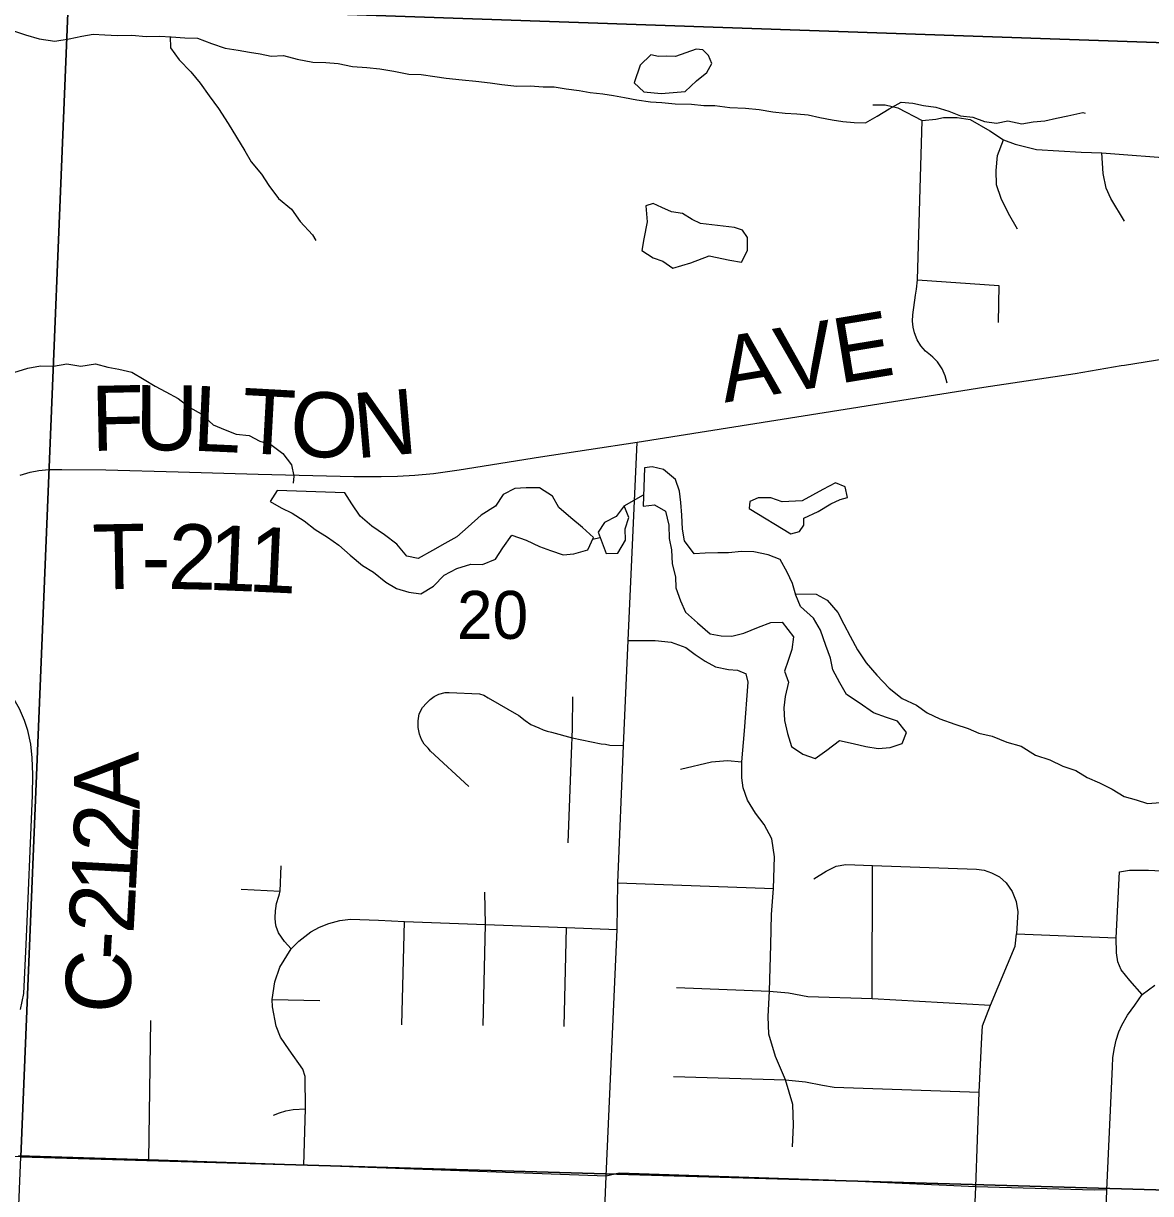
# Model space of a CAD drawing. Extents: x 0 to 34, y 0 to 22.
# Drawn here: x 4.185 to 5.169, y 16.95 to 17.972 of the extents above; entities that cross this region are included whole.
import ezdxf

# ---------------------------------------------------------------- set-up
doc = ezdxf.new("R2010")
doc.units = 0
for name, color, linetype in [('GM_X_Corporation', 7, 'Continuous'), ('GM_X_County_Road', 7, 'Continuous'), ('GM_X_County_Road_Text', 7, 'Continuous'), ('GM_X_Minor_Lake', 7, 'Continuous'), ('GM_X_Minor_River', 7, 'Continuous'), ('GM_X_Section_Text', 7, 'Continuous'), ('GM_X_Township_Road', 7, 'Continuous'), ('GM_X_Township_Road_Text', 7, 'Continuous')]:
    doc.layers.add(name, color=color, linetype=linetype)

msp = doc.modelspace()

# ---------------------------------------------------------------- linework, layer by layer
at = {"layer": 'GM_X_Corporation'}
for points in [[(5.2829, 18.9603), (5.2412, 17.9526), (4.2238, 17.9879), (4.2642, 18.9963)], [(3.1939, 18.0257), (4.2238, 17.9879), (4.1823, 16.9818), (3.1533, 17.0117), (3.155, 17.0299)], [(4.2238, 17.9879), (5.2412, 17.9526), (5.2034, 16.9522), (4.1823, 16.9818)], [(5.2034, 16.9522), (5.1967, 16.4715), (5.1712, 15.9307), (4.1402, 15.964), (4.1823, 16.9818)]]:
    msp.add_lwpolyline(points, close=True, dxfattribs=at)
at = {"layer": 'GM_X_County_Road'}
msp.add_lwpolyline([(4.1822, 17.1107), (4.185, 17.1244), (4.187, 17.1674), (4.1889, 17.2076), (4.1909, 17.2557), (4.1925, 17.2974), (4.1929, 17.3158), (4.1924, 17.3302), (4.1911, 17.3422), (4.1884, 17.3542), (4.1856, 17.3629), (4.1811, 17.3732), (4.1755, 17.3833), (4.169, 17.3936), (4.16, 17.4071), (4.1385, 17.4387), (4.132, 17.4487), (4.1243, 17.4624), (4.1222, 17.4744)], dxfattribs=at)
at = {"layer": 'GM_X_Minor_Lake'}
for points in [[(4.754, 17.9427), (4.7464, 17.943), (4.7392, 17.9426), (4.7324, 17.9441), (4.7233, 17.935), (4.7181, 17.9198), (4.7265, 17.9118), (4.7416, 17.9104), (4.7625, 17.912), (4.7723, 17.9215), (4.7814, 17.9287), (4.7859, 17.9367), (4.7828, 17.9436), (4.7779, 17.9485), (4.7722, 17.9492)], [(4.7722, 17.9492), (4.754, 17.9427)], [(4.7759, 17.797), (4.7687, 17.8004), (4.7603, 17.8057), (4.7505, 17.8072), (4.7421, 17.8109), (4.7345, 17.8143), (4.7281, 17.8124), (4.7293, 17.7983), (4.7263, 17.7835), (4.7248, 17.7733), (4.7347, 17.7669), (4.7431, 17.7639), (4.7518, 17.7578), (4.7674, 17.7624), (4.7836, 17.7686), (4.8015, 17.7648), (4.8117, 17.763), (4.817, 17.7732), (4.8169, 17.7846), (4.8127, 17.7911), (4.8055, 17.7933)], [(4.8055, 17.7933), (4.7759, 17.797)], [(4.7259, 17.5501), (4.7357, 17.5512), (4.7452, 17.5456), (4.7483, 17.5335), (4.7484, 17.5217), (4.7507, 17.5118), (4.7511, 17.4997), (4.7542, 17.4883), (4.7543, 17.4788), (4.7585, 17.4674), (4.7627, 17.4576), (4.7734, 17.4481), (4.7844, 17.4387), (4.7939, 17.4368), (4.8034, 17.4365), (4.8136, 17.4392), (4.8265, 17.4445), (4.8374, 17.4484), (4.8473, 17.4488), (4.8572, 17.4359), (4.8557, 17.4249), (4.8524, 17.4154), (4.8494, 17.4059), (4.8528, 17.3964), (4.8499, 17.3839), (4.8488, 17.374), (4.8492, 17.363), (4.8519, 17.3516), (4.8554, 17.3403), (4.8653, 17.3335), (4.8759, 17.3297), (4.8861, 17.3369), (4.8974, 17.3453), (4.9092, 17.3427), (4.9202, 17.3401), (4.9312, 17.3386), (4.9415, 17.3394), (4.9521, 17.3429), (4.9558, 17.3524), (4.9478, 17.3622), (4.9383, 17.3656), (4.9269, 17.3697), (4.9144, 17.3784), (4.9033, 17.3856), (4.8976, 17.3958), (4.8915, 17.4072), (4.8895, 17.4174), (4.8853, 17.4284), (4.8807, 17.4417), (4.8746, 17.4523), (4.8632, 17.4625), (4.8593, 17.4724), (4.8562, 17.4826), (4.8516, 17.4925), (4.8455, 17.5034), (4.8349, 17.5076), (4.8224, 17.5102), (4.8117, 17.5105), (4.8004, 17.5094), (4.7909, 17.5093), (4.7799, 17.5089), (4.7704, 17.5085), (4.762, 17.5198), (4.7601, 17.5301), (4.7597, 17.5422), (4.7588, 17.5532), (4.7577, 17.5631), (4.7542, 17.5733), (4.7435, 17.582), (4.7337, 17.5843), (4.7269, 17.5835)], [(4.7269, 17.5835), (4.7259, 17.5501)], [(4.4062, 17.5637), (4.4001, 17.5542), (4.4097, 17.5485), (4.4192, 17.544), (4.4298, 17.5372), (4.4393, 17.5296), (4.4503, 17.5229), (4.4602, 17.5161), (4.4701, 17.5074), (4.4808, 17.4983), (4.4903, 17.4923), (4.501, 17.4836), (4.5105, 17.4783), (4.5211, 17.4749), (4.5317, 17.4734), (4.5427, 17.4803), (4.5521, 17.4898), (4.5631, 17.4956), (4.5752, 17.4994), (4.5854, 17.4991), (4.5968, 17.5037), (4.6032, 17.5136), (4.6111, 17.5246), (4.6236, 17.5205), (4.6354, 17.5148), (4.6449, 17.5114), (4.6559, 17.5077), (4.6654, 17.5085), (4.6775, 17.5119), (4.6824, 17.5226), (4.6729, 17.5313), (4.6626, 17.54), (4.6523, 17.549), (4.6466, 17.5589), (4.6352, 17.5661), (4.6238, 17.566), (4.6139, 17.5656), (4.6037, 17.5602), (4.597, 17.55), (4.5845, 17.5423), (4.5731, 17.532), (4.563, 17.5233), (4.5527, 17.5175), (4.5418, 17.5114), (4.5293, 17.5045), (4.5194, 17.5064), (4.5107, 17.517), (4.5, 17.5249), (4.489, 17.5325), (4.4787, 17.5412), (4.4714, 17.5522), (4.4653, 17.5616)], [(4.8549, 17.5259), (4.8625, 17.5278), (4.8662, 17.5335), (4.8662, 17.5396), (4.8787, 17.5453), (4.8897, 17.5522), (4.898, 17.556), (4.9044, 17.5576), (4.9021, 17.567), (4.8938, 17.5704), (4.8828, 17.5647), (4.8646, 17.5548), (4.8472, 17.5539), (4.8373, 17.5573), (4.8263, 17.5573), (4.8191, 17.5542), (4.8184, 17.5481)], [(4.4653, 17.5616), (4.4062, 17.5637)], [(4.6935, 17.5086), (4.7037, 17.509), (4.7105, 17.5204), (4.71, 17.5303), (4.7134, 17.5402), (4.7092, 17.5504), (4.7024, 17.5409), (4.6922, 17.5359), (4.6865, 17.5275)], [(4.8184, 17.5481), (4.8549, 17.5259)], [(4.6865, 17.5275), (4.6935, 17.5086)]]:
    msp.add_lwpolyline(points, dxfattribs=at)
at = {"layer": 'GM_X_Minor_River'}
for points in [[(4.1768, 17.9648), (4.1863, 17.9615), (4.1985, 17.9581), (4.2121, 17.9562), (4.2246, 17.9582), (4.2356, 17.9605), (4.2455, 17.9621), (4.2557, 17.9617), (4.2667, 17.961), (4.2792, 17.9614), (4.2917, 17.9603), (4.3035, 17.9604), (4.3137, 17.96), (4.3255, 17.9589), (4.3365, 17.9586), (4.349, 17.9541), (4.3608, 17.95), (4.3722, 17.9481), (4.382, 17.9466), (4.3915, 17.9451), (4.401, 17.9429), (4.4116, 17.9437), (4.4238, 17.9403), (4.4374, 17.9377), (4.4488, 17.9374), (4.4594, 17.9367), (4.4719, 17.9341), (4.4845, 17.933), (4.4958, 17.9319), (4.508, 17.93), (4.5213, 17.9274), (4.5319, 17.9271), (4.544, 17.9252), (4.5539, 17.9237), (4.5679, 17.9223), (4.5797, 17.9212), (4.5922, 17.9197), (4.6025, 17.9182), (4.6154, 17.9167), (4.6271, 17.9172), (4.6385, 17.9161), (4.648, 17.9161), (4.6586, 17.9146), (4.67, 17.9131), (4.6795, 17.9113), (4.6905, 17.9102), (4.6999, 17.9087), (4.7094, 17.9068), (4.7204, 17.905), (4.7322, 17.9031), (4.7421, 17.9024), (4.7538, 17.9013), (4.7679, 17.901), (4.7789, 17.8999), (4.7883, 17.8999), (4.8016, 17.8981), (4.8153, 17.8977), (4.827, 17.8963), (4.8392, 17.8944), (4.8498, 17.8933), (4.86, 17.8926), (4.8699, 17.8919), (4.8801, 17.8893), (4.8908, 17.8874), (4.9003, 17.8859), (4.9101, 17.8852), (4.92, 17.8848), (4.9302, 17.8906), (4.9408, 17.8971), (4.951, 17.9028), (4.9612, 17.9021), (4.9707, 17.8998), (4.9813, 17.8984), (4.9927, 17.895), (5.003, 17.8908), (5.0136, 17.8897), (5.0239, 17.886), (5.0345, 17.8845), (5.0443, 17.8864), (5.0565, 17.8838), (5.0663, 17.8858), (5.0766, 17.8866), (5.0868, 17.8889), (5.0966, 17.8908), (5.1099, 17.8939), (5.1118, 17.8931)], [(4.3128, 17.9601), (4.313, 17.9502), (4.3206, 17.9399), (4.3309, 17.9294), (4.3389, 17.9195), (4.3469, 17.9085), (4.355, 17.8972), (4.3634, 17.8843), (4.3706, 17.8722), (4.3779, 17.8604), (4.3836, 17.8506), (4.3924, 17.84), (4.3989, 17.8301), (4.4073, 17.8188), (4.4187, 17.8093), (4.4263, 17.7987), (4.437, 17.787), (4.44, 17.7821)], [(4.1763, 17.6668), (4.1884, 17.6707), (4.1994, 17.6726), (4.2108, 17.6723), (4.2225, 17.6742), (4.2347, 17.6724), (4.2475, 17.6743), (4.2582, 17.6713), (4.268, 17.6698), (4.2794, 17.6672), (4.2901, 17.6608), (4.2996, 17.6548), (4.3091, 17.6499), (4.3197, 17.6442), (4.33, 17.6363), (4.3399, 17.6306), (4.3502, 17.6212), (4.3608, 17.6167), (4.3703, 17.6129), (4.3817, 17.6118), (4.3912, 17.6069), (4.4007, 17.6039), (4.4113, 17.596), (4.4186, 17.5861), (4.4209, 17.5763), (4.4202, 17.5701)], [(4.7092, 17.5504), (4.7262, 17.56)], [(4.6817, 17.5212), (4.6883, 17.5228)], [(4.859, 17.4734), (4.8768, 17.4732), (4.8866, 17.4679), (4.8958, 17.4573), (4.9011, 17.4471), (4.9065, 17.4365), (4.913, 17.4247), (4.9206, 17.4134), (4.9298, 17.4024), (4.9408, 17.3911), (4.9519, 17.382), (4.9644, 17.3763), (4.9739, 17.3695), (4.9849, 17.3643), (4.9979, 17.3598), (5.0096, 17.356), (5.0191, 17.3519), (5.0305, 17.3493), (5.0434, 17.344), (5.056, 17.3406), (5.0685, 17.3327), (5.081, 17.3286), (5.0924, 17.3229), (5.1038, 17.3192), (5.1137, 17.3131), (5.1244, 17.3086), (5.1354, 17.3029), (5.146, 17.2965), (5.1563, 17.2935), (5.1662, 17.2905), (5.1775, 17.2913)]]:
    msp.add_lwpolyline(points, dxfattribs=at)
at = {"layer": 'GM_X_Township_Road'}
for p, q in [((4.9258, 17.1201), (4.9262, 17.2364)), ((4.7036, 17.2213), (4.8396, 17.2162)), ((4.3749, 17.2157), (4.4087, 17.2139)), ((4.5151, 17.0973), (4.5174, 17.1874)), ((4.6568, 17.0958), (4.6589, 17.1821)), ((5.052, 17.1765), (5.1388, 17.1731)), ((4.4019, 17.1194), (4.4436, 17.1184)), ((4.2942, 16.9792), (4.296, 17.1009))]:
    msp.add_line(p, q, dxfattribs=at)
for points in [[(4.9265, 17.9006), (4.9372, 17.9004), (4.9481, 17.8978), (4.9694, 17.8868), (4.9813, 17.8879), (4.9881, 17.8894), (5.0001, 17.8894), (5.0115, 17.8877), (5.0285, 17.8777), (5.0404, 17.8699), (5.0507, 17.8662), (5.0694, 17.8615), (5.1084, 17.8591), (5.1265, 17.8586), (5.1948, 17.8534), (5.2396, 17.8514)], [(4.9913, 17.6576), (4.9897, 17.6639), (4.987, 17.6701), (4.9828, 17.6761), (4.9787, 17.6802), (4.9767, 17.6818), (4.9723, 17.6855), (4.9683, 17.6901), (4.9651, 17.6953), (4.9627, 17.7014), (4.9615, 17.7064), (4.961, 17.7115), (4.9612, 17.7172), (4.9637, 17.7342), (4.9644, 17.7396), (4.9653, 17.7476), (4.9694, 17.8868)], [(5.0527, 17.792), (5.0448, 17.8055), (5.0386, 17.8188), (5.0345, 17.8306), (5.0341, 17.8432), (5.0354, 17.8564), (5.0404, 17.8699)], [(5.1462, 17.799), (5.1343, 17.8187), (5.1303, 17.8278), (5.1275, 17.8406), (5.1265, 17.8586)], [(4.9653, 17.7476), (5.0365, 17.7427), (5.0359, 17.7105)], [(5.1463, 17.6733), (5.2202, 17.685), (5.235, 17.686), (5.3232, 17.6883), (5.3916, 17.6861), (5.5192, 17.6811)], [(4.1819, 17.577), (4.1905, 17.5797), (4.1982, 17.5811), (4.2069, 17.582), (4.2183, 17.5822), (4.2565, 17.5819), (4.3199, 17.5801), (4.3895, 17.5779), (4.4732, 17.5761), (4.4969, 17.576), (4.5114, 17.5763), (4.5263, 17.577), (4.5427, 17.5787), (4.5652, 17.5818), (4.6362, 17.5931), (4.7206, 17.6059), (5.0232, 17.6539), (5.1031, 17.666), (5.1433, 17.6729), (5.1463, 17.6733)], [(4.6689, 16.2797), (4.669, 16.2837), (4.6747, 16.4412), (4.6781, 16.5323), (4.6789, 16.5559), (4.6855, 16.7695), (4.6863, 16.7882), (4.6883, 16.8362), (4.6935, 16.965), (4.703, 17.1804), (4.7036, 17.2213), (4.7087, 17.341), (4.7128, 17.4329), (4.7206, 17.6059)], [(4.7128, 17.4329), (4.7364, 17.4329), (4.7504, 17.4312), (4.763, 17.4266), (4.7713, 17.4206), (4.78, 17.4146), (4.789, 17.4099), (4.8003, 17.4073), (4.8083, 17.4069), (4.8159, 17.4036)], [(4.8372, 17.167), (4.8379, 17.1936), (4.8396, 17.2162), (4.8404, 17.2438), (4.8383, 17.2595), (4.8315, 17.2722), (4.8239, 17.2819), (4.8169, 17.2932), (4.8133, 17.3041), (4.8119, 17.3128), (4.8119, 17.3268), (4.8143, 17.354), (4.8176, 17.3963), (4.8159, 17.4036)], [(4.5736, 17.3053), (4.5402, 17.3362), (4.5381, 17.3387), (4.5346, 17.3421), (4.5323, 17.3462), (4.5304, 17.351), (4.5292, 17.3568), (4.5292, 17.3625), (4.5302, 17.3686), (4.5331, 17.3744), (4.5366, 17.3781), (4.5397, 17.3813), (4.5432, 17.3839), (4.5474, 17.3859), (4.553, 17.3873), (4.5563, 17.3875), (4.5828, 17.3862), (4.5867, 17.3849), (4.5905, 17.3827), (4.6173, 17.3672)], [(4.6602, 17.2562), (4.6636, 17.3415), (4.6638, 17.3479), (4.664, 17.3563), (4.6644, 17.3835)], [(4.6173, 17.3672), (4.6229, 17.3628), (4.6278, 17.3593), (4.6347, 17.3564), (4.6384, 17.3549), (4.642, 17.3537), (4.6459, 17.3526), (4.6638, 17.3479)], [(4.6638, 17.3479), (4.6893, 17.3426), (4.6929, 17.3421), (4.6967, 17.3414), (4.7087, 17.341)], [(4.7584, 17.3204), (4.7856, 17.3268), (4.7996, 17.3281), (4.8119, 17.3268)], [(5.1419, 17.2309), (5.1505, 17.2323), (5.1671, 17.2322), (5.1728, 17.2318), (5.182, 17.2317), (5.1891, 17.2316), (5.194, 17.2319), (5.2007, 17.2325), (5.2093, 17.2336), (5.2169, 17.2348), (5.2259, 17.2367), (5.239, 17.2403), (5.2514, 17.2448), (5.2629, 17.2495), (5.2724, 17.2534), (5.2774, 17.2549), (5.284, 17.2558), (5.3334, 17.2589)], [(4.4184, 17.1635), (4.4125, 17.1699), (4.4073, 17.1775), (4.4053, 17.1831), (4.4047, 17.1862), (4.4044, 17.1905), (4.4048, 17.1967), (4.405, 17.1987), (4.4057, 17.203), (4.4078, 17.2094), (4.4083, 17.2115), (4.4087, 17.2139), (4.4098, 17.236)], [(4.8748, 17.2247), (4.8855, 17.2314), (4.8943, 17.2357), (4.9029, 17.2372), (4.9262, 17.2364), (5.0168, 17.2332), (5.0237, 17.2323), (5.0301, 17.2299), (5.037, 17.2265), (5.0428, 17.2211), (5.048, 17.2135), (5.0517, 17.205), (5.053, 17.1959), (5.052, 17.1765)], [(5.1616, 17.1237), (5.1508, 17.1359), (5.1434, 17.1453), (5.1404, 17.1522), (5.1393, 17.1601), (5.1388, 17.1731), (5.1419, 17.2309)], [(4.586, 17.0966), (4.5882, 17.1849), (4.5875, 17.213)], [(4.4294, 16.9746), (4.431, 17.0238), (4.4308, 17.052), (4.4286, 17.0584), (4.4168, 17.0753), (4.4091, 17.0864), (4.4053, 17.096), (4.4022, 17.1128), (4.4019, 17.1194), (4.4042, 17.1347), (4.4084, 17.1474), (4.4184, 17.1635), (4.4252, 17.1702), (4.4355, 17.1783), (4.4433, 17.1824), (4.4513, 17.1857), (4.461, 17.1884), (4.4703, 17.1894), (4.4946, 17.1886), (4.5174, 17.1874), (4.5882, 17.1849), (4.6589, 17.1821), (4.703, 17.1804)], [(5.0136, 16.8961), (5.0163, 16.9558), (5.0193, 17.0383), (5.0215, 17.0865), (5.0223, 17.0963), (5.0291, 17.1142), (5.0508, 17.166), (5.052, 17.1765)], [(4.8561, 16.9905), (4.857, 17.0096), (4.8566, 17.0275), (4.8502, 17.0491), (4.8413, 17.0695), (4.8357, 17.0891), (4.8349, 17.1044), (4.8362, 17.1265), (4.8372, 17.167)], [(4.755, 17.1299), (4.8362, 17.1265), (4.8527, 17.1252), (4.8697, 17.1218), (4.9258, 17.1201), (5.0291, 17.1142)], [(5.1285, 16.8801), (5.1308, 16.953), (5.1357, 17.0606), (5.136, 17.0685), (5.1373, 17.0771), (5.1388, 17.0839), (5.1413, 17.091), (5.1439, 17.097), (5.1488, 17.1057), (5.1552, 17.1143), (5.1616, 17.1237), (5.1728, 17.1318)], [(4.7524, 17.0521), (4.8502, 17.0491), (4.8676, 17.0474), (4.8825, 17.0445), (4.8927, 17.0428), (5.0193, 17.0383)], [(4.4029, 17.0183), (4.4082, 17.0202), (4.4137, 17.0221), (4.4201, 17.0233), (4.431, 17.0238)], [(5.1308, 16.953), (5.12, 16.9527), (5.0163, 16.9558), (4.8876, 16.9614), (4.7049, 16.9677), (4.6935, 16.965), (4.4294, 16.9746), (4.2942, 16.9792), (4.1804, 16.9828)]]:
    msp.add_lwpolyline(points, dxfattribs=at)

# ---------------------------------------------------------------- texts
at = {"layer": 'GM_X_County_Road_Text'}
for s, rotation, p in [('A', 90.9857, (4.2861, 17.2853)), ('2', 87.3646, (4.2845, 17.2464)), ('1', 86.9975, (4.2826, 17.2111)), ('2', 86.8562, (4.2807, 17.176)), ('-', 86.8153, (4.2794, 17.1526)), ('C', 86.8134, (4.2768, 17.106))]:
    msp.add_text(s, height=0.0568, rotation=rotation, dxfattribs=at).set_placement(p)
at = {"layer": 'GM_X_Section_Text'}
msp.add_text('20', height=0.04186, rotation=0, dxfattribs=at).set_placement((4.5632, 17.4342))
at = {"layer": 'GM_X_Township_Road_Text'}
for s, height, rotation, p in [('AVE', 0.05682, 9.4074, (4.7971, 17.6404)), ('F', 0.0568, 1.2117, (4.2443, 17.5982)), ('U', 0.0568, 359.5701, (4.2822, 17.599)), ('L', 0.0568, 357.4107, (4.3317, 17.5986)), ('T', 0.0568, 356.8741, (4.374, 17.5967)), ('O', 0.0568, 356.8656, (4.4164, 17.5944)), ('N', 0.0568, 4.921, (4.4751, 17.5918)), ('T', 0.0568, 1.0629, (4.2454, 17.4772)), ('2', 0.0568, 358.7197, (4.3106, 17.4779)), ('1', 0.0568, 357.6888, (4.3454, 17.4771)), ('1', 0.0568, 357.3658, (4.3803, 17.4757)), ('-', 0.0568, 359.7814, (4.2876, 17.478))]:
    msp.add_text(s, height=height, rotation=rotation, dxfattribs=at).set_placement(p)

doc.saveas('drawing.dxf')
